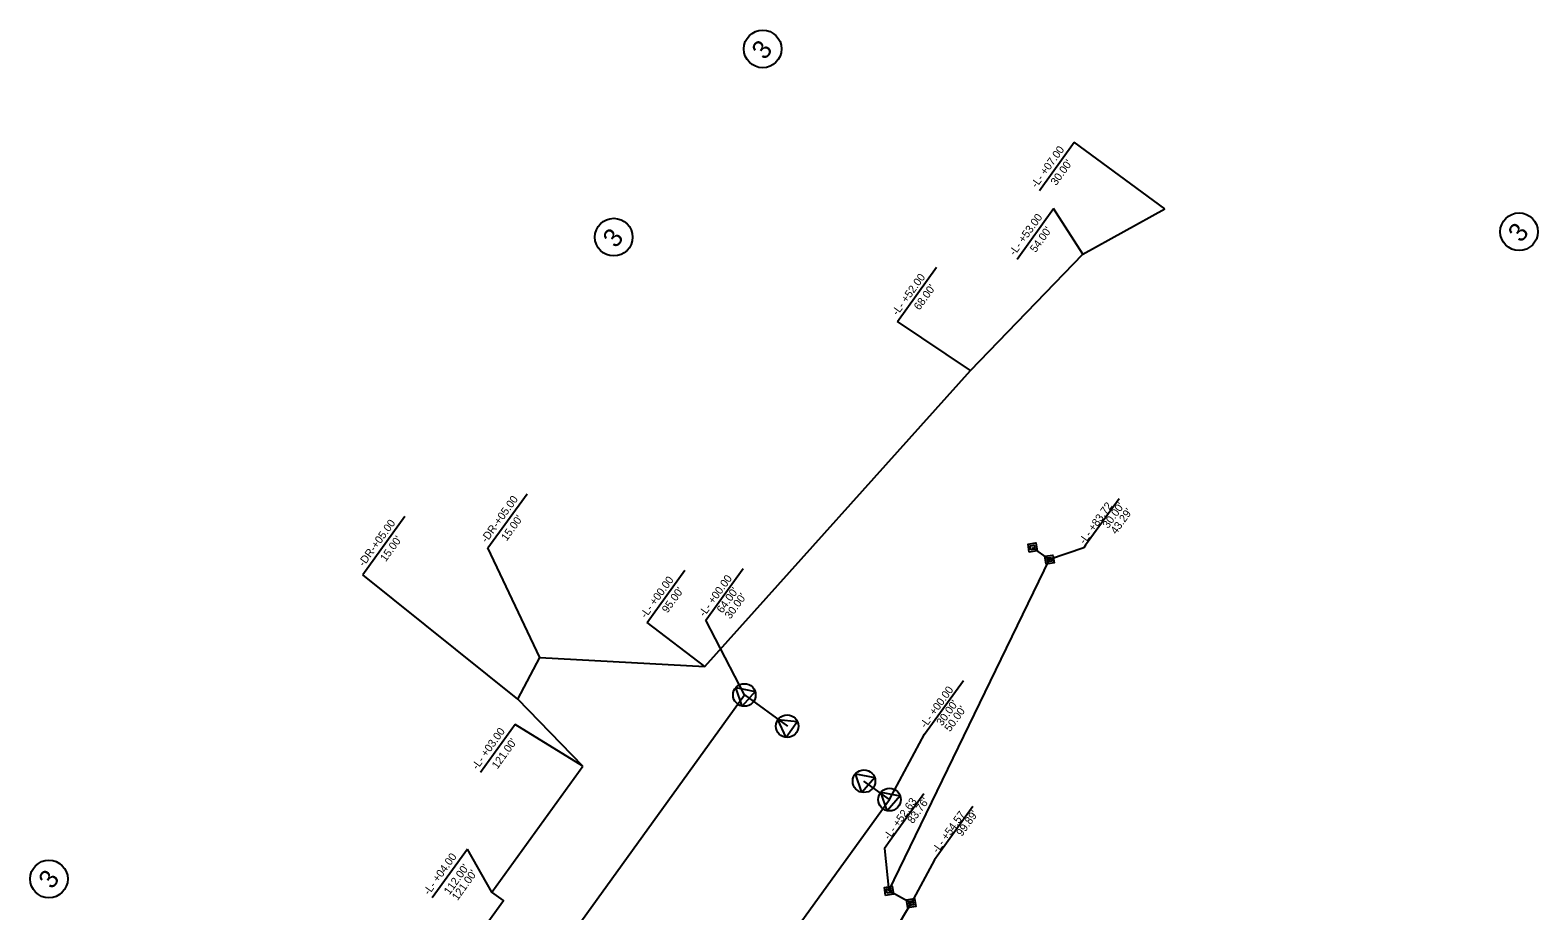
# Model space of a CAD drawing. Extents: x 2189745 to 2190978, y 387331 to 388613.
# Drawn here: x 2190017 to 2190978, y 388052 to 388613 of the extents above; entities that cross this region are included whole.
import ezdxf

# ---------------------------------------------------------------- set-up
doc = ezdxf.new("R2010")
doc.units = 0
for name, color, linetype in [('Prop Easement Construction', 7, 'Continuous'), ('Prop Easement Construction Station Offsets', 7, 'Continuous'), ('Prop Easement Permanent Utility', 7, 'Continuous'), ('Prop Easement Permanent Utility Station Offsets', 7, 'Continuous'), ('Prop Parcel Number CELL', 7, 'Continuous'), ('Prop Parcel Number Text', 7, 'Continuous'), ('Prop ROW Marker CELL', 7, 'Continuous'), ('Prop ROW Permanent Easement CELL', 7, 'Continuous'), ('Prop ROW RW Lines', 7, 'Continuous'), ('Prop ROW Station Offsets', 7, 'Continuous')]:
    doc.layers.add(name, color=color, linetype=linetype)

msp = doc.modelspace()

# ---------------------------------------------------------------- linework, layer by layer
at = {"layer": 'Prop Easement Construction'}
for p, q in [((2190687.48, 388470.39), (2190739.88, 388499.3)), ((2190616, 388396.12), (2190687.48, 388470.39)), ((2190446.7, 388207.52), (2190616, 388396.12)), ((2190327.47, 388186.7), (2190341.49, 388213.22)), ((2190341.49, 388213.22), (2190446.7, 388207.52)), ((2190368.88, 388144.05), (2190327.47, 388186.7))]:
    msp.add_line(p, q, dxfattribs=at)
msp.add_lwpolyline([(2190217.66, 387918.98), (2190318.27, 388058.49), (2190310.97, 388063.75), (2190368.88, 388144.05)], dxfattribs=at)
at = {"layer": 'Prop Easement Construction Station Offsets'}
for p, q in [((2190659.97, 388510.79), (2190681.95, 388541.59)), ((2190739.88, 388499.3), (2190681.95, 388541.59)), ((2190645.65, 388467.18), (2190668.84, 388499.34)), ((2190687.48, 388470.39), (2190668.84, 388499.34)), ((2190569.54, 388427.43), (2190594.39, 388461.93)), ((2190616, 388396.12), (2190569.54, 388427.43)), ((2190308.42, 388283.13), (2190333.36, 388317.58)), ((2190255.41, 388303.11), (2190228.66, 388265.97)), ((2190341.49, 388213.22), (2190308.42, 388283.13)), ((2190327.47, 388186.7), (2190228.66, 388265.97)), ((2190409.9, 388235.58), (2190433.93, 388268.84)), ((2190446.7, 388207.52), (2190409.9, 388235.58)), ((2190325.74, 388170.53), (2190303.68, 388139.91)), ((2190368.88, 388144.05), (2190325.74, 388170.53)), ((2190295.31, 388091.17), (2190272.87, 388060.02)), ((2190310.97, 388063.75), (2190295.31, 388091.17))]:
    msp.add_line(p, q, dxfattribs=at)
at = {"layer": 'Prop Easement Permanent Utility'}
for p, q in [((2190563.98, 388064.54), (2190666.33, 388275.64)), ((2190666.33, 388275.64), (2190655.55, 388283.41)), ((2190578.21, 388056.67), (2190563.98, 388064.54)), ((2190567.89, 388039.45), (2190578.21, 388056.67))]:
    msp.add_line(p, q, dxfattribs=at)
at = {"layer": 'Prop Easement Permanent Utility Station Offsets'}
for p, q in [((2190710.72, 388314.49), (2190689.34, 388284.84)), ((2190586.29, 388126.36), (2190564.81, 388096.58)), ((2190617.5, 388118.24), (2190595.86, 388088.24))]:
    msp.add_line(p, q, dxfattribs=at)
for points in [[(2190689.34, 388284.84), (2190688.14, 388283.18), (2190666.33, 388275.64)], [(2190564.81, 388096.58), (2190561.19, 388091.57), (2190563.98, 388064.54)], [(2190595.86, 388088.24), (2190593.01, 388084.28), (2190578.21, 388056.67)]]:
    msp.add_lwpolyline(points, dxfattribs=at)
at = {"layer": 'Prop Parcel Number CELL'}
for p, q in [((2190483.52, 388601.07), (2190483.52, 388601.07)), ((2190388.61, 388481.15), (2190388.61, 388481.15)), ((2190965.58, 388484.63), (2190965.58, 388484.63)), ((2190028.64, 388072.12), (2190028.64, 388072.12))]:
    msp.add_line(p, q, dxfattribs=at)
for centre in [(2190483.52, 388601.07), (2190965.58, 388484.63), (2190388.61, 388481.15), (2190028.64, 388072.12)]:
    msp.add_circle(centre, 12, dxfattribs=at)
at = {"layer": 'Prop ROW Marker CELL'}
for p, q in [((2190471.85, 388189.38), (2190471.85, 388189.38)), ((2190499.12, 388169.5), (2190499.12, 388169.5)), ((2190548.09, 388134.4), (2190548.09, 388134.4)), ((2190564.31, 388122.7), (2190564.31, 388122.7))]:
    msp.add_line(p, q, dxfattribs=at)
for points in [[(2190470.42, 388182.31), (2190466.44, 388194.14), (2190478.68, 388191.7)], [(2190498.39, 388162.32), (2190493.28, 388173.71), (2190505.69, 388172.46)], [(2190546.66, 388127.33), (2190542.68, 388139.15), (2190554.92, 388136.72)], [(2190562.89, 388115.63), (2190558.9, 388127.45), (2190571.14, 388125.02)]]:
    msp.add_lwpolyline(points, close=True, dxfattribs=at)
for centre in [(2190471.85, 388189.38), (2190499.12, 388169.5), (2190548.09, 388134.4), (2190564.31, 388122.7)]:
    msp.add_circle(centre, 7.2, dxfattribs=at)
at = {"layer": 'Prop ROW Permanent Easement CELL'}
for p, q in [((2190655.55, 388283.41), (2190655.55, 388283.41)), ((2190666.33, 388275.64), (2190666.33, 388275.64)), ((2190563.98, 388064.54), (2190563.98, 388064.54)), ((2190578.21, 388056.67), (2190578.21, 388056.67))]:
    msp.add_line(p, q, dxfattribs=at)
for points in [[(2190653.45, 388280.49), (2190652.63, 388285.52), (2190657.66, 388286.33), (2190658.47, 388281.31)], [(2190654.5, 388281.95), (2190654.09, 388284.47), (2190656.6, 388284.87), (2190657.01, 388282.36)], [(2190664.23, 388272.72), (2190663.41, 388277.75), (2190668.44, 388278.56), (2190669.25, 388273.53)], [(2190665.28, 388274.18), (2190664.87, 388276.69), (2190667.38, 388277.1), (2190667.79, 388274.59)], [(2190561.88, 388061.62), (2190561.06, 388066.64), (2190566.09, 388067.46), (2190566.9, 388062.43)], [(2190562.93, 388063.08), (2190562.52, 388065.59), (2190565.04, 388066), (2190565.44, 388063.48)], [(2190576.1, 388053.75), (2190575.29, 388058.78), (2190580.31, 388059.59), (2190581.13, 388054.57)], [(2190577.15, 388055.21), (2190576.75, 388057.72), (2190579.26, 388058.13), (2190579.67, 388055.62)]]:
    msp.add_lwpolyline(points, close=True, dxfattribs=at)
at = {"layer": 'Prop ROW RW Lines'}
for p, q in [((2190564.31, 388122.7), (2190548.09, 388134.4)), ((2190505.82, 388041.59), (2190564.31, 388122.7))]:
    msp.add_line(p, q, dxfattribs=at)
msp.add_lwpolyline([(2190142.61, 387674.73), (2190115.04, 387694.62), (2190471.85, 388189.38), (2190499.42, 388169.5)], dxfattribs=at)
at = {"layer": 'Prop ROW Station Offsets'}
for p, q in [((2190447.3, 388236.99), (2190471.08, 388269.99)), ((2190471.85, 388189.38), (2190447.3, 388236.99)), ((2190586.66, 388164.34), (2190611.46, 388198.7)), ((2190564.31, 388122.7), (2190586.66, 388164.34))]:
    msp.add_line(p, q, dxfattribs=at)

# ---------------------------------------------------------------- texts
at = {"layer": 'Prop Easement Construction Station Offsets'}
for s, rotation, p in [('-L- +07.00', 54.01795, (2190658.05, 388512.16)), ("30.00'", 54.01795, (2190670.6, 388513.69)), ('-L- +53.00', 54.01795, (2190644.1, 388469.01)), ("54.00'", 54.01795, (2190657.45, 388470.96)), ('-L- +52.00', 54.01795, (2190569.44, 388430.83)), ("68.00'", 54.01795, (2190583.43, 388434.2)), ('-DR-+05.00', 54.01795, (2190307.5, 388286.01)), ("15.00'", 54.01795, (2190320.37, 388287.11)), ('-DR-+05.00', 54.01795, (2190229.3, 388270.84)), ("15.00'", 54.01795, (2190243.28, 388273.92)), ('-L- +00.00', 54.01795, (2190409.06, 388237.93)), ("95.00'", 54.01795, (2190422.83, 388241.21)), ('-L- +03.00', 54.22704, (2190301.65, 388141.37)), ("121.00'", 54.22704, (2190314.45, 388141.82)), ('-L- +04.00', 54.22704, (2190270.84, 388061.49)), ("112.00'", 54.22704, (2190283.96, 388061.71)), ("121.00'", 54.22704, (2190289.07, 388058.03))]:
    msp.add_text(s, height=5, rotation=rotation, dxfattribs=at).set_placement(p)
at = {"layer": 'Prop Easement Permanent Utility Station Offsets'}
for s, p in [('-L- +83.72', (2190688.73, 388285.11)), ("30.00'", (2190703.74, 388295.15)), ("43.29'", (2190708.85, 388291.46)), ('-L- +52.63', (2190564.11, 388096.72)), ("83.76'", (2190579.3, 388107.02)), ('-L- +54.57', (2190595.05, 388088.23)), ("99.89'", (2190610.51, 388098.89))]:
    msp.add_text(s, height=5, rotation=54.20184, dxfattribs=at).set_placement(p)
at = {"layer": 'Prop Parcel Number Text'}
for rotation, p in [(51.50112, (2190484.89, 388593.54)), (51.50112, (2190389.97, 388473.62)), (51.50112, (2190966.94, 388477.1)), (54.22704, (2190030.71, 388065.04))]:
    msp.add_text('3', height=12, rotation=rotation, dxfattribs=at).set_placement(p)
at = {"layer": 'Prop ROW Station Offsets'}
for s, p in [('-L- +00.00', (2190446.31, 388238.83)), ("64.00'", (2190457.79, 388241.09)), ("30.00'", (2190462.89, 388237.39)), ('-L- +00.00', (2190587.35, 388167.89)), ("30.00'", (2190597.85, 388169.27)), ("50.00'", (2190602.95, 388165.56))]:
    msp.add_text(s, height=5, rotation=54.01795, dxfattribs=at).set_placement(p)

doc.saveas('drawing.dxf')
